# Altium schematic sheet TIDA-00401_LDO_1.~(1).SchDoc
size 431 x 279 mm; Date: Not shown in title block; ApprovedBy: Not shown in title block; CheckedBy: Not shown in title block; Author: Not shown in title block; CompanyName: Not shown in title block; Engineer: Not shown in title block; Organization: Not shown in title block; Address1: Not shown in title block; Address2: Not shown in title block; Address3: Not shown in title block; Address4: Not shown in title block; DocumentNumber: 2; Revision: Use project parameter SCH_Rev; SheetNumber: 2; SheetTotal: 3; PageSetup: Record=PageOptions|CenterHorizontal=True|CenterVertical=True|PrintScale=1.00|XCorrection=1.00|YCorrection=1.00|PrintKind=0|BorderSize=5000000|LeftOffset=0|BottomOffset=0|Orientation=2|PaperLength=1000|PaperWidth=1000|Scale=100|PaperSource=15|PrintQuality=600|MediaType=1|DitherType=10|PaperKind=Letter|PrintScaleMode=1
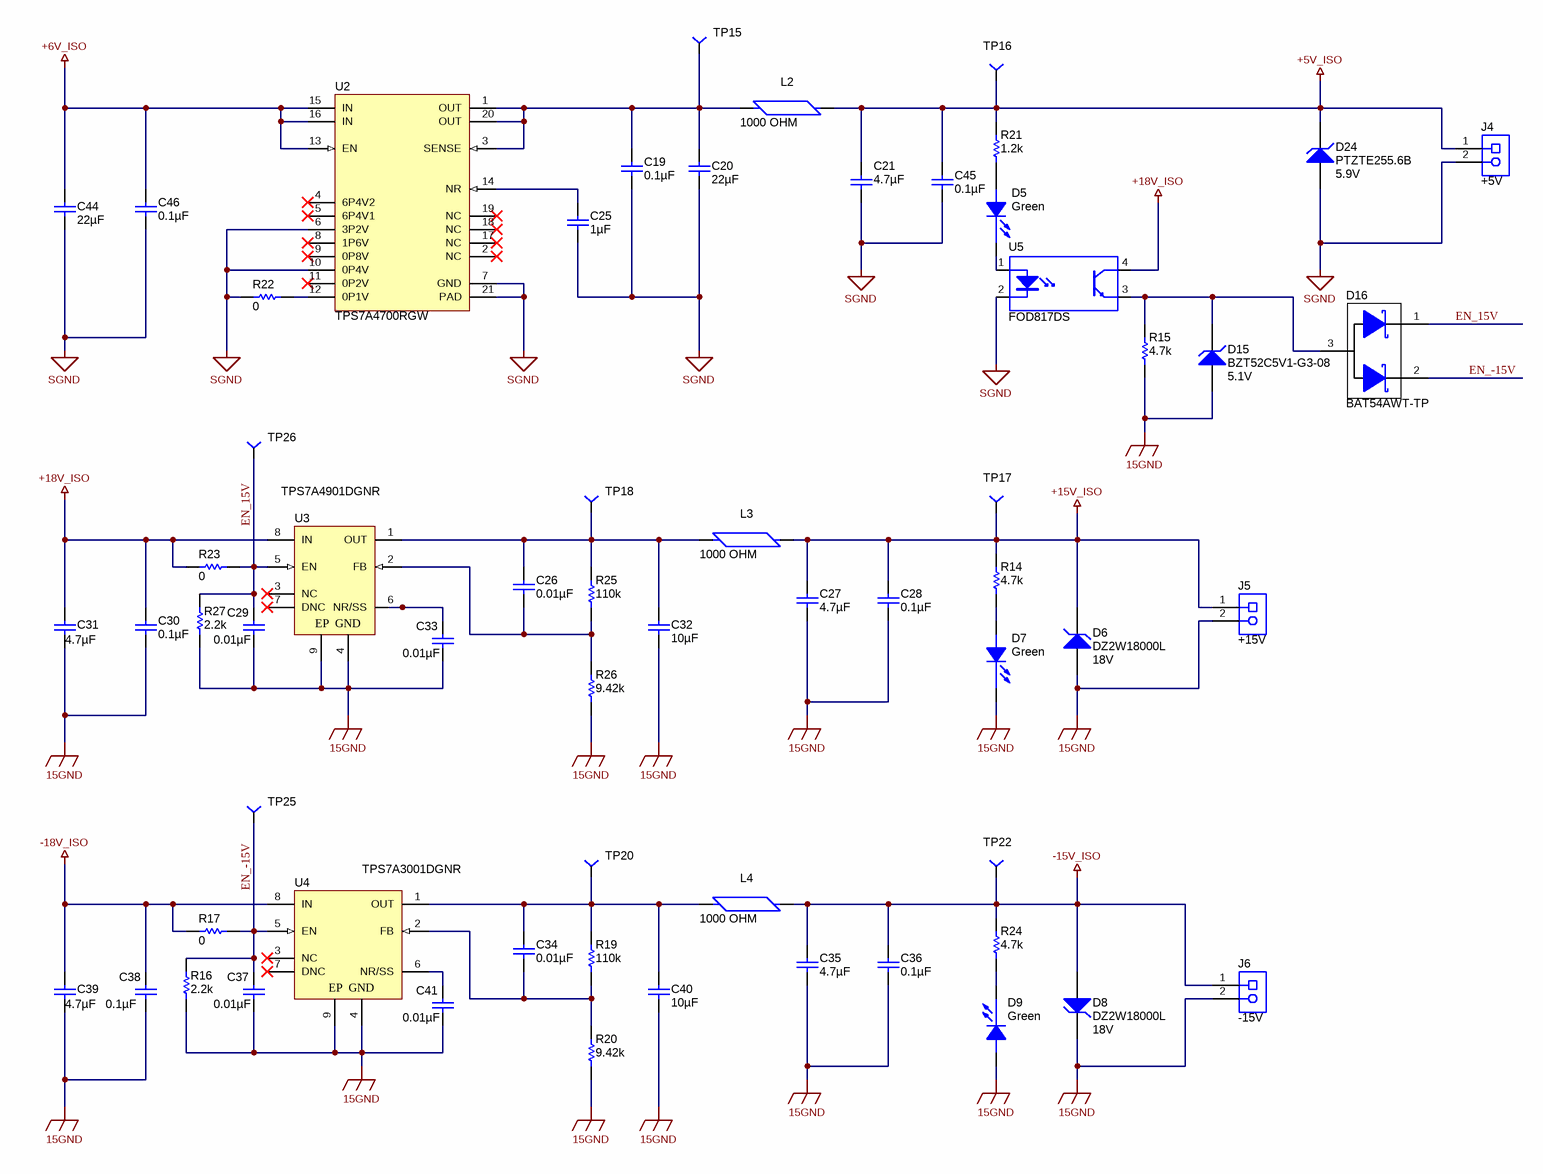
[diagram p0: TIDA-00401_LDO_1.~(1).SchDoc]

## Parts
C19  ValueDisplayed: 0.1µF  [0603]  (hidden comment: 06035C104KAT2A)
C20  ValueDisplayed: 22µF  [0805_HV]  (hidden comment: GRM21BR61C226ME44)
C21  ValueDisplayed: 4.7µF  [0805_HV]  (hidden comment: C2012X5R1H475K125AB)
C25  ValueDisplayed: 1µF  [0603]  (hidden comment: C1608X7R1E105K080AB)
C26  ValueDisplayed: 0.01µF  [0603]  (hidden comment: 06031C103JAT2A)
C27  ValueDisplayed: 4.7µF  [0805_HV]  (hidden comment: C2012X5R1H475K125AB)
C28  ValueDisplayed: 0.1µF  [0603]  (hidden comment: 06035C104KAT2A)
C29  ValueDisplayed: 0.01µF  [0603]  (hidden comment: 06031C103JAT2A)
C30  ValueDisplayed: 0.1µF  [0603]  (hidden comment: 06035C104KAT2A)
C31  ValueDisplayed: 4.7µF  [1206]  (hidden comment: GRM31CR71H475KA12L)
C32  ValueDisplayed: 10µF  [1206]  (hidden comment: GRM31CR71E106KA12L)
C33  ValueDisplayed: 0.01µF  [0603]  (hidden comment: 06031C103JAT2A)
C34  ValueDisplayed: 0.01µF  [0603]  (hidden comment: 06031C103JAT2A)
C35  ValueDisplayed: 4.7µF  [0805_HV]  (hidden comment: C2012X5R1H475K125AB)
C36  ValueDisplayed: 0.1µF  [0603]  (hidden comment: 06035C104KAT2A)
C37  ValueDisplayed: 0.01µF  [0603]  (hidden comment: 06031C103JAT2A)
C38  ValueDisplayed: 0.1µF  [0603]  (hidden comment: 06035C104KAT2A)
C39  ValueDisplayed: 4.7µF  [1206]  (hidden comment: GRM31CR71H475KA12L)
C40  ValueDisplayed: 10µF  [1206]  (hidden comment: GRM31CR71E106KA12L)
C41  ValueDisplayed: 0.01µF  [0603]  (hidden comment: 06031C103JAT2A)
C44  ValueDisplayed: 22µF  [0805_HV]  (hidden comment: GRM21BR61C226ME44)
C45  ValueDisplayed: 0.1µF  [0603]  (hidden comment: 06035C104KAT2A)
C46  ValueDisplayed: 0.1µF  [0603]  (hidden comment: 06035C104KAT2A)
D5  value Green  [LED0603AA]  (hidden comment: LED_LG L29K-G2J1-24-Z)
D6  DZ2W18000L  value 18V  [SOD-123]
D7  value Green  [LED0603AA]  (hidden comment: LED_LG L29K-G2J1-24-Z)
D8  DZ2W18000L  value 18V  [SOD-123]
D9  value Green  [LED0603AA]  (hidden comment: LED_LG L29K-G2J1-24-Z)
D15  BZT52C5V1-G3-08  value 5.1V  [SOD-123]
D16  BAT54AWT-TP  [SOT-323]
D24  PTZTE255.6B  value 5.9V  [powerDI123]
J4  +5V  [PhoenixConact_1727010]
J5  +15V  [PhoenixConact_1727010]
J6  -15V  [PhoenixConact_1727010]
L2  1000 OHM  [FB0603]
L3  1000 OHM  [FB0603]
L4  1000 OHM  [FB0603]
R14  value 4.7k  [0603]  (hidden comment: CRCW06034K70JNEA)
R15  value 4.7k  [0603]  (hidden comment: CRCW06034K70JNEA)
R16  ValueDisplayed: 2.2k  [0603]  (hidden comment: CRCW06032K20JNEA)
R17  ValueDisplayed: 0  [0603]  (hidden comment: CRCW06030000Z0EA)
R19  value 110k  [0603]  (hidden comment: CRCW0402110KFKED)
R20  value 9.42k  [0603]  (hidden comment: TNPW04029K42BEED)
R21  value 1.2k  [0402]  (hidden comment: CRCW04021K20JNED)
R22  ValueDisplayed: 0  [0603]  (hidden comment: CRCW06030000Z0EA)
R23  ValueDisplayed: 0  [0603]  (hidden comment: CRCW06030000Z0EA)
R24  value 4.7k  [0603]  (hidden comment: CRCW06034K70JNEA)
R25  value 110k  [0603]  (hidden comment: CRCW0402110KFKED)
R26  value 9.42k  [0603]  (hidden comment: TNPW04029K42BEED)
R27  ValueDisplayed: 2.2k  [0603]  (hidden comment: CRCW06032K20JNEA)
TP15  TP1_PD40_D0.5_S50  [TP1_PD40_D0.5_S50]  (value not drawn)
TP16  TP-038  [TP1_PD40_D0.5_S50]  (value not drawn)
TP17  TP-038  [TP1_PD40_D0.5_S50]  (value not drawn)
TP18  TP1_PD40_D0.5_S50  [TP1_PD40_D0.5_S50]  (value not drawn)
TP20  TP1_PD40_D0.5_S50  [TP1_PD40_D0.5_S50]  (value not drawn)
TP22  TP-038  [TP1_PD40_D0.5_S50]  (value not drawn)
TP25  TP1_PD40_D0.5_S50  [TP1_PD40_D0.5_S50]  (value not drawn)
TP26  TP1_PD40_D0.5_S50  [TP1_PD40_D0.5_S50]  (value not drawn)
U2  TPS7A4700RGW  [RGW0020A]
U3  TPS7A4901DGNR  [DGN0008D_N]
U4  TPS7A3001DGNR  [DGN0008D_N]
U5  FOD817DS  [N04C]

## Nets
15GND: C27.1 C28.1 C29.2 C30.1 C31.2 C32.2 C33.2 C35.1 C36.1 C37.2 C38.1 C39.2 C40.2 C41.2 D6.2(A) D7.1(C) D8.1(K) D9.2(A) D15.2(A) J5.2 J6.2 R15.2 R16.1 R20.2 R26.2 R27.1 U3.4(GND) U3.9(EP) U4.4(GND) U4.9(EP)
+5V_ISO: C21.1 C45.2 D24.1(K) J4.1 L2.2 R21.1 TP16.1
+6V_ISO: C44.1 C46.2 U2.13(EN) U2.15(IN) U2.16(IN)
+15V_ISO: C27.2 C28.2 D6.1(K) J5.1 L3.2 R14.1 TP17.1
+18V_ISO: C30.2 C31.1 R23.2 U3.8(IN) U5.4(C)
-15V_ISO: C35.2 C36.2 D8.2(A) J6.1 L4.2 R24.1 TP22.1
-18V_ISO: C38.2 C39.1 R17.2 U4.8(IN)
SGND: C19.1 C20.2 C21.2 C25.2 C44.2 C45.1 C46.1 D24.2(A) J4.2 R22.2 U2.6(3P2V) U2.7(GND) U2.10(0P4V) U2.21(PAD) U5.2(K)
EN_15V: C29.1 D16.1(A) R23.1 R27.2 TP26.1 U3.5(EN)
EN_-15V: C37.1 D16.2(K) R16.2 R17.1 TP25.1 U4.5(EN)
NetC19_2: C19.2 C20.1 L2.1 TP15.1 U2.1(OUT) U2.3(SENSE) U2.20(OUT)
NetC25_1: C25.1 U2.14(NR)
NetC26_1: C26.1 C32.1 L3.1 R25.1 TP18.1 U3.1(OUT)
NetC26_2: C26.2 R25.2 R26.1 U3.2(FB)
NetC33_1: C33.1 U3.6(NR/SS)
NetC34_1: C34.1 C40.1 L4.1 R19.1 TP20.1 U4.1(OUT)
NetC34_2: C34.2 R19.2 R20.1 U4.2(FB)
NetC41_1: C41.1 U4.6(NR/SS)
NetD5_1: D5.1(C) U5.1(A)
NetD5_2: D5.2(A) R21.2
NetD7_2: D7.2(A) R14.2
NetD9_1: D9.1(C) R24.2
NetD15_1: D15.1(K) D16.3(A) R15.1 U5.3(E)
NetR22_1: R22.1 U2.12(0P1V)

Not connected (* = marked no-connect by the designer): U2 2(NC)* 4(6P4V2)* 5(6P4V1)* 8(1P6V)* 9(0P8V)* 11(0P2V)* 17(NC)* 18(NC)* 19(NC)*; U3 3(NC)* 7(DNC)*; U4 3(NC)* 7(DNC)*

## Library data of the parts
C19 C28 C30 C36 C38 C45 C46 = 06035C104KAT2A: CAP, CERM, 0.1uF, 50V, +/-10%, X7R, 0603; Manufacturer: AVX; Polarized: N; CompType: Capacitor; U/M: EA; Cap_F: 0.0000001; Tolerance_%: 10; Value1: Unknown; VDC_V: 50; TaMin_C: -55; TaMax_C: 125
C20 C44 = GRM21BR61C226ME44: CAP, CERM, 22uF, 16V, +/-20%, X5R, 0805; Manufacturer: MuRata; Polarized: N; CompType: Capacitor; U/M: EA; Cap_F: 0.000022; Tolerance_%: 20; Value1: Unknown; VDC_V: 16; TaMin_C: -55; TaMax_C: 85; Cap_Case: 0805
C21 C27 C35 = C2012X5R1H475K125AB: CAP, CERM, 4.7uF, 50V, +/-10%, X5R, 0805; Manufacturer: TDK; Polarized: N; CompType: Capacitor; U/M: EA; Cap_F: 0.0000047; Tolerance_%: 10; Value1: Unknown; VDC_V: 50; TaMin_C: -55; TaMax_C: 85; Cap_Case: 0805
C25 = C1608X7R1E105K080AB: CAP, CERM, 1uF, 25V, +/-10%, X7R, 0603; Manufacturer: TDK; Polarized: N; CompType: Capacitor; U/M: EA; Cap_F: 0.000001; Tolerance_%: 10; Value1: Unknown; VDC_V: 25; TaMin_C: -55; TaMax_C: 125
C26 C29 C33 C34 C37 C41 = 06031C103JAT2A: CAP, CERM, 0.01uF, 100V, +/-5%, X7R, 0603; Manufacturer: AVX; Polarized: N; CompType: Capacitor; U/M: EA; Cap_F: 0.00000001; Tolerance_%: 5; ESR_Ohm: 0.098; Value1: 0.098 ohm; VDC_V: 100; TaMin_C: -55; TaMax_C: 125
C31 C39 = GRM31CR71H475KA12L: CAP, CERM, 4.7uF, 50V, +/-10%, X7R, 1206; Manufacturer: MuRata; Polarized: N; CompType: Capacitor; U/M: EA; Cap_F: 0.0000047; Tolerance_%: 10; Value1: Unknown; VDC_V: 50; TaMin_C: -55; TaMax_C: 125; Cap_Case: 2220
C32 C40 = GRM31CR71E106KA12L: CAP, CERM, 10uF, 25V, +/-10%, X7R, 1206; Manufacturer: MuRata; Polarized: N; CompType: Capacitor; U/M: EA; Cap_F: 0.00001; Tolerance_%: 10; Value1: Unknown; VDC_V: 25; TaMin_C: -55; TaMax_C: 125; Cap_Case: 2220
D5 D7 D9 = LED_LG L29K-G2J1-24-Z: LED SmartLED Green 570NM; Manufacturer: OSRAM; SymbolCreator: x0120606
D6 D8 = DZ2W18000L: Diode, Zener, 18V, 1W, SOD-123; Manufacturer: Panasonic
D15 = BZT52C5V1-G3-08: Diode, Zener, 5.1 V, 500 mW, SOD-123; Manufacturer: Vishay-Semiconductor; SymbolCreator: a0412235; U/M: EA; Power_W: 0.5; Vz_V: 5.1; Value1: 0.5W; RJA_CperW: 300
D16 = BAT54AWT-TP: Diode, Schottky, 30 V, 0.2 A, SOT-323; Manufacturer: Micro Commercial Components; SymbolCreator: a0412235; U/M: EA; Vf_V: 1; Value: 30V; Value1: 0.2A; Value2: 1V; Io_A: 0.2; Vr_V: 30; TJmax_C: 125; RJC_CperW: 500
D24 = PTZTE255.6B: DIODE ZENER 5.9V 1W PMDS; Manufacturer: Rohm Semiconductor; U/M: EA; Vz_V: 5.9
J4-J6 = 1727010: Conn Term Block, 2POS, 3.81mm, TH; Manufacturer: Phoenix Contact; SymbolCreator: a0412235; Value: 2x1; CompType: Terminal Block; U/M: EA
L2 = MMZ1608B102C: FERRITE CHIP 1000 OHM 1500MA 0805; PartNumber: MPZ2012S102AT000; Manufacturer: TDK Corporation; CompType: Ferrite Bead
L3 L4 = MMZ1608B102C: FERRITE CHIP 1000 OHM 300MA 0603; Manufacturer: TDK Corporation; CompType: Ferrite Bead
R14 R15 R24 = CRCW06034K70JNEA: RES, 4.7k ohm, 5%, 0.1W, 0603; Manufacturer: Vishay-Dale; CompType: Resistor; Res_ohm: 4700; Value_Code: 4k70; Tolerance_%: 5; Power_W: 0.1; VDC_V: 75; TempCo: 200 ppm/C; EIA_Code: E24; U/M: EA
R16 R27 = CRCW06032K20JNEA: RES, 2.2 k, 5%, 0.1 W, 0603; Manufacturer: Vishay-Dale; CompType: Resistor; Value: 2.2k; Res_ohm: 2200; Value_Code: 2k20; Tolerance_%: 5; Power_W: 0.1; Value2: 0.1W; VDC_V: 75; TempCo: 200 ppm/C; EIA_Code: E24; U/M: EA
R17 R22 R23 = CRCW06030000Z0EA: RES, 0, 5%, 0.1 W, 0603; Manufacturer: Vishay-Dale; CompType: Resistor; Value: 0; Value_Code: 0000; Tolerance_%: 5; Power_W: 0.1; Value2: 0.1W; VDC_V: 75; TempCo: 200 ppm/C; EIA_Code: E24; U/M: EA
R19 R25 = CRCW0402110KFKED: RES, 110k ohm, 1%, 0.063W, 0402; Manufacturer: Vishay-Dale; CompType: Resistor; Res_ohm: 110000; Tolerance_%: 1; Power_W: 0.063; VDC_V: 50; TempCo: 100 ppm/C; EIA_Code: E96; U/M: EA
R20 R26 = CRCW04029K31FKED: RES, 9.42k ohm, 1%, 0.063W, 0402; Manufacturer: Vishay-Dale; CompType: Resistor; Res_ohm: 9310; Value_Code: 9k42; Tolerance_%: 1; Power_W: 0.063; VDC_V: 50; TempCo: 100 ppm/C; EIA_Code: E96; U/M: EA
R21 = CRCW04021K20JNED: RES, 1.2k ohm, 5%, 0.063W, 0402; Manufacturer: Vishay-Dale; CompType: Resistor; Res_ohm: 1200; Value_Code: 1k20; Tolerance_%: 5; Power_W: 0.063; VDC_V: 50; TempCo: 200 ppm/C; EIA_Code: E24; U/M: EA
TP15 TP18 TP20 TP25 TP26 = TP-040_RND: Test Point 40mil pad 20mil drill; Manufacturer: STD; Description: Test Point, O.040 Hole; Value: STD
TP16 TP17 TP22 = TP-038: Test Point 40mil pad 20mil drill; Manufacturer: STD; Value: STD
U2 = TPS7A4700RGW: 36-V, 1-A, 4.17-µVRMS, RF LDO Voltage Regulator, RGW0020A; Manufacturer: Texas Instruments; SymbolCreator: a0412235; CompType: IC; U/M: EA
U3 = TPS7A4901DGNR: Single Output High PSRR LDO, 150 mA, Adjustable 1.2 to 33 V Output, 3 to 36 V Input, with Ultra-Low Noise, 8-pin MSOP (DGN), -40 to 125 degC, Green (RoHS & no Sb/Br); Manufacturer: Texas Instruments; Alternate Manufacturer: None; Alternate PartNumber: Equivalent; Accuracy(%): 1.5; Iout(Max)(A): 0.15; Iq(Typ)(mA): 0.06; Power Good: TRUE; SubFamily: Single Channel LDO; Vdo(Typ)(mV): 260; Vin(Max)(V): 36; Vin(Min)(V): 3; Vout Adj(Max)(V): 33; Vout Adj(Min)(V): 1.2
U4 = TPS7A3001DGNR: Single Output High PSRR LDO, 200 mA, Adjustable -1.18 to -33 V Output, -3 to -36 V Input, with Ultra-Low Noise, 8-pin MSOP (DGN), -40 to 125 degC, Green (RoHS & no Sb/Br); Manufacturer: Texas Instruments; Alternate Manufacturer: None; Alternate PartNumber: Equivalent; Accuracy(%): 1.5; Iout(Max)(A): 0.2; Iq(Typ)(mA): 0.05; SubFamily: Single Channel LDO; Vdo(Typ)(mV): 216
U5 = FOD817DS: Optocoupler, 5kV RMS, SMT; Manufacturer: Fairchild Semiconductor; U/M: EA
